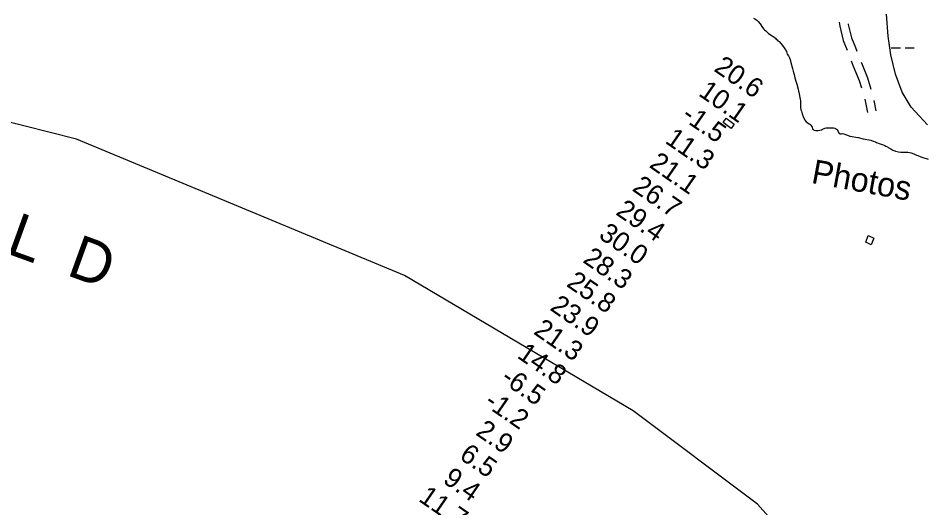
# Model space of a CAD drawing. Extents: x 3192927 to 3230760, y 831141 to 856475.
# Drawn here: x 3203837 to 3206954, y 851843 to 853534 of the extents above; entities that cross this region are included whole.
import ezdxf

# ---------------------------------------------------------------- set-up
doc = ezdxf.new("R2010")
doc.units = 0
for name, color, linetype in [('V-BLDG-OTLN', 7, 'Continuous'), ('V-RIVR-IDEN', 7, 'Continuous'), ('V-RIVR-RANG', 7, 'Continuous'), ('V-ROAD-CNTR', 7, 'Continuous'), ('V-SITE-VEGE', 7, 'Continuous'), ('V-TOPO-BNDY', 7, 'Continuous'), ('V-TOPO-SHOR', 7, 'Continuous'), ('V-WETL-SWMP', 7, 'Continuous')]:
    doc.layers.add(name, color=color, linetype=linetype)

msp = doc.modelspace()

# ---------------------------------------------------------------- linework, layer by layer
at = {"layer": 'V-BLDG-OTLN'}
for points in [[(3206296.2, 853152.6), (3206268.5, 853173.2), (3206279.7, 853188.3), (3206307.4, 853167.7)], [(3206761.2, 852760.6), (3206769.4, 852783.7), (3206788.4, 852774.2), (3206778.9, 852751.1)]]:
    msp.add_lwpolyline(points, close=True, dxfattribs=at)
at = {"layer": 'V-ROAD-CNTR'}
for p, q in [((3206757.4, 853253.9), (3206766.6, 853207.2)), ((3206788.9, 853249.2), (3206796, 853213))]:
    msp.add_line(p, q, dxfattribs=at)
for points in [[(3206669.3, 853518.9), (3206671, 853505.6), (3206682.9, 853455.7), (3206696.1, 853422.9)], [(3206700.2, 853514), (3206700.6, 853510.9), (3206711.5, 853464.8), (3206725, 853431.4), (3206729.9, 853418.9)], [(3206710.7, 853385.7), (3206717.7, 853367.8), (3206738.2, 853317.7), (3206745.9, 853292.2)], [(3206744.5, 853381.6), (3206745.5, 853378.9), (3206766.5, 853327.8), (3206778.6, 853287.8)]]:
    msp.add_lwpolyline(points, dxfattribs=at)
at = {"layer": 'V-SITE-VEGE'}
for p, q in [((3206373.9, 853533.5), (3206378.3, 853531)), ((3206378.3, 853531), (3206384.7, 853526.4)), ((3206384.7, 853526.4), (3206389.4, 853521.9)), ((3206389.4, 853521.9), (3206396.2, 853513.3)), ((3206396.2, 853513.3), (3206398.5, 853509.8)), ((3206398.5, 853509.8), (3206402.3, 853504.5)), ((3206402.3, 853504.5), (3206408.5, 853496.4)), ((3206408.5, 853496.4), (3206411.4, 853493.3)), ((3206411.4, 853493.3), (3206415.9, 853489)), ((3206415.9, 853489), (3206422.5, 853483.1)), ((3206422.5, 853483.1), (3206425.4, 853480.7)), ((3206425.4, 853480.7), (3206437.8, 853471.7)), ((3206437.8, 853471.7), (3206443.2, 853468.3)), ((3206443.2, 853468.3), (3206449, 853463.6)), ((3206449, 853463.6), (3206451.3, 853461.2)), ((3206451.3, 853461.2), (3206455.4, 853458.1)), ((3206455.4, 853458.1), (3206457.9, 853455.5)), ((3206457.9, 853455.5), (3206461.6, 853452.4)), ((3206461.6, 853452.4), (3206469.2, 853444.2)), ((3206469.2, 853444.2), (3206476.9, 853434.7)), ((3206476.9, 853434.7), (3206479.8, 853430.4)), ((3206479.8, 853430.4), (3206483.4, 853424.4)), ((3206483.4, 853424.4), (3206485.4, 853421.6)), ((3206485.4, 853421.6), (3206486.9, 853418.3)), ((3206486.9, 853418.3), (3206490, 853408.7)), ((3206490, 853408.7), (3206493.8, 853403.1)), ((3206493.8, 853403.1), (3206497.3, 853396)), ((3206497.3, 853396), (3206499.6, 853390)), ((3206499.6, 853390), (3206502.4, 853380.4)), ((3206502.4, 853380.4), (3206508.1, 853359.1)), ((3206508.1, 853359.1), (3206510.8, 853350.7)), ((3206510.8, 853350.7), (3206513.1, 853342.1)), ((3206513.1, 853342.1), (3206514.2, 853338.6)), ((3206514.2, 853338.6), (3206516.7, 853327.7)), ((3206516.7, 853327.7), (3206521.1, 853312.6)), ((3206521.1, 853312.6), (3206523.4, 853305.4)), ((3206523.4, 853305.4), (3206527.5, 853287.8)), ((3206527.5, 853287.8), (3206528.8, 853281.2)), ((3206528.8, 853281.2), (3206529.8, 853277.3)), ((3206529.8, 853277.3), (3206531.8, 853266)), ((3206531.8, 853266), (3206533.9, 853257.9)), ((3206533.9, 853257.9), (3206534.7, 853254.4)), ((3206534.7, 853254.4), (3206535.6, 853248.2)), ((3206535.6, 853248.2), (3206536, 853243.7)), ((3206536.1, 853237.3), (3206535.9, 853225.4)), ((3206536, 853243.7), (3206536.1, 853237.3)), ((3206535.9, 853225.4), (3206536.6, 853216.6)), ((3206536.6, 853216.6), (3206538.9, 853211.9)), ((3206538.9, 853211.9), (3206541.4, 853203.5)), ((3206541.4, 853203.5), (3206545, 853193.9)), ((3206545, 853193.9), (3206547.5, 853188.1)), ((3206547.5, 853188.1), (3206552.1, 853179.7)), ((3206552.1, 853179.7), (3206555.6, 853175.5)), ((3206555.6, 853175.5), (3206567.4, 853166.9)), ((3206567.4, 853166.9), (3206571.3, 853163.5)), ((3206571.3, 853163.5), (3206573.6, 853160.8)), ((3206573.6, 853160.8), (3206576.3, 853156.5)), ((3206576.3, 853156.5), (3206577.5, 853152.8)), ((3206577.5, 853152.8), (3206577.8, 853148.9)), ((3206577.8, 853148.9), (3206582.7, 853146.3)), ((3206582.7, 853146.3), (3206588.7, 853145.1)), ((3206588.7, 853145.1), (3206596.3, 853145.4)), ((3206596.3, 853145.4), (3206607.6, 853148.3)), ((3206607.6, 853148.3), (3206611.9, 853150)), ((3206611.9, 853150), (3206616.8, 853152.3)), ((3206616.8, 853152.3), (3206619.8, 853153.3)), ((3206619.8, 853153.3), (3206624.1, 853154.4)), ((3206624.1, 853154.4), (3206633.2, 853155.1)), ((3206633.2, 853155.1), (3206636.9, 853154.9)), ((3206636.9, 853154.9), (3206645.1, 853155.2)), ((3206645.1, 853155.2), (3206649.2, 853155)), ((3206649.2, 853155), (3206653.7, 853153.8)), ((3206653.7, 853153.8), (3206656.8, 853152)), ((3206656.8, 853152), (3206659.3, 853150.2)), ((3206659.3, 853150.2), (3206662.6, 853147.3)), ((3206662.6, 853147.3), (3206665.3, 853142.2)), ((3206665.3, 853142.2), (3206667.2, 853138.1)), ((3206667.2, 853138.1), (3206669.5, 853135)), ((3206669.5, 853135), (3206672.4, 853133.6)), ((3206672.4, 853133.6), (3206676.5, 853134.1)), ((3206676.5, 853134.1), (3206679.5, 853134.9)), ((3206679.5, 853134.9), (3206684.7, 853133.9)), ((3206684.7, 853133.9), (3206690.6, 853131.9)), ((3206690.6, 853131.9), (3206697.9, 853128.9)), ((3206697.9, 853128.9), (3206705.3, 853126.3)), ((3206705.3, 853126.3), (3206713.9, 853124.3)), ((3206713.9, 853124.3), (3206726.8, 853122.7)), ((3206726.8, 853122.7), (3206734.3, 853121.3)), ((3206734.3, 853121.3), (3206751.7, 853117.1)), ((3206751.7, 853117.1), (3206771.1, 853113.2)), ((3206771.1, 853113.2), (3206777.9, 853111.6)), ((3206777.9, 853111.6), (3206785.9, 853109)), ((3206785.9, 853109), (3206793.9, 853106.2)), ((3206793.9, 853106.2), (3206797.8, 853104.6)), ((3206797.8, 853104.6), (3206801.5, 853103.5)), ((3206801.5, 853103.5), (3206807.1, 853101.1)), ((3206807.1, 853101.1), (3206817, 853097.5)), ((3206817, 853097.5), (3206820.9, 853095.7)), ((3206820.9, 853095.7), (3206826.7, 853093.3)), ((3206826.7, 853093.3), (3206830, 853091.6)), ((3206830, 853091.6), (3206835.3, 853089.2)), ((3206835.3, 853089.2), (3206838.2, 853087.2)), ((3206838.2, 853087.2), (3206847.5, 853081.9)), ((3206847.5, 853081.9), (3206854.7, 853078.1)), ((3206854.7, 853078.1), (3206860.7, 853075.4)), ((3206860.7, 853075.4), (3206863.6, 853074.4)), ((3206863.6, 853074.4), (3206873.8, 853072)), ((3206873.8, 853072), (3206881.2, 853071.1)), ((3206881.2, 853071.1), (3206885.4, 853070.9)), ((3206885.4, 853070.9), (3206888.6, 853070.5)), ((3206888.6, 853070.5), (3206892.7, 853070.5)), ((3206892.7, 853070.5), (3206899.1, 853071)), ((3206899.1, 853071), (3206905.3, 853070.6)), ((3206905.3, 853070.6), (3206911.4, 853069.5)), ((3206911.4, 853069.5), (3206916.8, 853068.3)), ((3206916.8, 853068.3), (3206926.9, 853064.6)), ((3206926.9, 853064.6), (3206935.7, 853060.6)), ((3206935.7, 853060.6), (3206940.1, 853058.8)), ((3206940.1, 853058.8), (3206950.4, 853055.2)), ((3206950.4, 853055.2), (3206954.3, 853053.7)), ((3206954.3, 853053.7), (3206976.3, 853046.3))]:
    msp.add_line(p, q, dxfattribs=at)
at = {"layer": 'V-TOPO-BNDY'}
for p, q in [((3204038.5, 853115.2), (3202468.5, 853515)), ((3205169.6, 852645.1), (3204038.5, 853115.2)), ((3205958.2, 852178.5), (3205169.6, 852645.1)), ((3206387.9, 851856.1), (3205958.2, 852178.5)), ((3206709.1, 851495.9), (3206387.9, 851856.1))]:
    msp.add_line(p, q, dxfattribs=at)
at = {"layer": 'V-TOPO-SHOR'}
for points in [[(3206373.9, 853533.5), (3206378.3, 853531), (3206384.7, 853526.4), (3206389.4, 853521.9), (3206396.2, 853513.3), (3206398.5, 853509.8), (3206402.3, 853504.5), (3206408.5, 853496.4), (3206411.4, 853493.3), (3206415.9, 853489), (3206422.5, 853483.1), (3206425.4, 853480.7), (3206437.8, 853471.7), (3206443.2, 853468.3), (3206449, 853463.6), (3206451.3, 853461.2), (3206455.4, 853458.1), (3206457.9, 853455.5), (3206461.6, 853452.4), (3206469.2, 853444.2), (3206476.9, 853434.7)], [(3206476.9, 853434.7), (3206479.8, 853430.4), (3206483.4, 853424.4), (3206485.4, 853421.6), (3206486.9, 853418.3), (3206490, 853408.7), (3206493.8, 853403.1), (3206497.3, 853396), (3206499.6, 853390), (3206502.4, 853380.4), (3206508.1, 853359.1), (3206510.8, 853350.7), (3206513.1, 853342.1), (3206514.2, 853338.6), (3206516.7, 853327.7), (3206521.1, 853312.6), (3206523.4, 853305.4), (3206527.5, 853287.8), (3206528.8, 853281.2), (3206529.8, 853277.3), (3206531.8, 853266), (3206533.9, 853257.9), (3206534.7, 853254.4), (3206535.6, 853248.2), (3206536, 853243.7), (3206536.1, 853237.3), (3206535.9, 853225.4), (3206536.6, 853216.6), (3206538.9, 853211.9), (3206541.4, 853203.5), (3206545, 853193.9), (3206547.5, 853188.1), (3206552.1, 853179.7), (3206555.6, 853175.5), (3206567.4, 853166.9), (3206571.3, 853163.5), (3206573.6, 853160.8), (3206576.3, 853156.5), (3206577.5, 853152.8), (3206577.8, 853148.9), (3206582.7, 853146.3), (3206588.7, 853145.1), (3206596.3, 853145.4), (3206607.6, 853148.3), (3206611.9, 853150), (3206616.8, 853152.3), (3206619.8, 853153.3), (3206624.1, 853154.4), (3206633.2, 853155.1), (3206636.9, 853154.9), (3206645.1, 853155.2), (3206649.2, 853155), (3206653.7, 853153.8), (3206656.8, 853152), (3206659.3, 853150.2), (3206662.6, 853147.3), (3206665.3, 853142.2), (3206667.2, 853138.1), (3206669.5, 853135), (3206672.4, 853133.6), (3206676.5, 853134.1), (3206679.5, 853134.9), (3206684.7, 853133.9), (3206690.6, 853131.9), (3206697.9, 853128.9), (3206705.3, 853126.3), (3206713.9, 853124.3), (3206726.8, 853122.7), (3206734.3, 853121.3), (3206751.7, 853117.1), (3206771.1, 853113.2), (3206777.9, 853111.6), (3206785.9, 853109), (3206793.9, 853106.2), (3206797.8, 853104.6), (3206801.5, 853103.5), (3206807.1, 853101.1), (3206817, 853097.5), (3206820.9, 853095.7), (3206826.7, 853093.3), (3206830, 853091.6), (3206835.3, 853089.2), (3206838.2, 853087.2), (3206847.5, 853081.9), (3206854.7, 853078.1), (3206860.7, 853075.4), (3206863.6, 853074.4), (3206873.8, 853072), (3206881.2, 853071.1), (3206885.4, 853070.9), (3206888.6, 853070.5), (3206892.7, 853070.5), (3206899.1, 853071), (3206905.3, 853070.6), (3206911.4, 853069.5), (3206916.8, 853068.3), (3206926.9, 853064.6), (3206935.7, 853060.6), (3206940.1, 853058.8), (3206950.4, 853055.2), (3206954.3, 853053.7)], [(3206954.3, 853053.7), (3206976.3, 853046.3)]]:
    msp.add_lwpolyline(points, dxfattribs=at)
at = {"layer": 'V-WETL-SWMP'}
for p, q in [((3206838.2, 853471.1), (3206831.9, 853546.9)), ((3206847.6, 853406.1), (3206838.2, 853471.1)), ((3206848.2, 853430.4), (3206880.2, 853430.4)), ((3206896.2, 853430.4), (3206928.2, 853430.4)), ((3206862.9, 853340.1), (3206847.6, 853406.1)), ((3206886, 853278), (3206862.9, 853340.1)), ((3206917.2, 853226.6), (3206886, 853278)), ((3206973.8, 853165.2), (3206917.2, 853226.6))]:
    msp.add_line(p, q, dxfattribs=at)

# ---------------------------------------------------------------- texts
at = {"layer": 'V-RIVR-IDEN'}
for s, height, rotation, p in [('Photos', 83, 349.6413, (3206570, 852964.9)), ('O  L  D', 150, 340.0708, (3203539, 852815.1))]:
    msp.add_text(s, height=height, rotation=rotation, dxfattribs=at).set_placement(p)
at = {"layer": 'V-RIVR-RANG'}
for s, p in [('20.6', (3206233.7, 853353.1)), ('10.1', (3206180.5, 853268.3)), ('-1.5', (3206121.9, 853187.2)), ('11.3', (3206065.2, 853104.9)), ('21.1', (3206010.5, 853021.1)), ('26.7', (3205951.9, 852940.1)), ('29.4', (3205895.2, 852857.7)), ('30.0', (3205836.1, 852777)), ('28.3', (3205781.8, 852692.9)), ('25.8', (3205725.1, 852610.5)), ('23.9', (3205668.2, 852528.3)), ('21.3', (3205611.8, 852445.8)), ('14.8', (3205555.1, 852363.4)), ('-6.5', (3205498.4, 852281)), ('-1.2', (3205441.7, 852198.6)), ('2.9', (3205412.2, 852097.5)), ('6.5', (3205355.7, 852014.9)), ('9.4', (3205299, 851932.6)), ('11.7', (3205215, 851869.1))]:
    msp.add_text(s, height=67, rotation=325.3283, dxfattribs=at).set_placement(p)

doc.saveas('drawing.dxf')
